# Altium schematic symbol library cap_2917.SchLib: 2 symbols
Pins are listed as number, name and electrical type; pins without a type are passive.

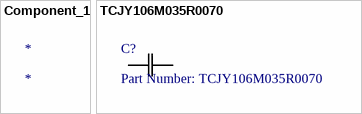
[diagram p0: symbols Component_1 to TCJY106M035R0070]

## Component_1
designator *

## TCJY106M035R0070
designator C?, comment Part Number: TCJY106M035R0070
No Description Available; Vendor: AVX Corporation; Built_By: EMA_UL_Team; Type: DEV
footprint TCJY
pins: 1, 2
